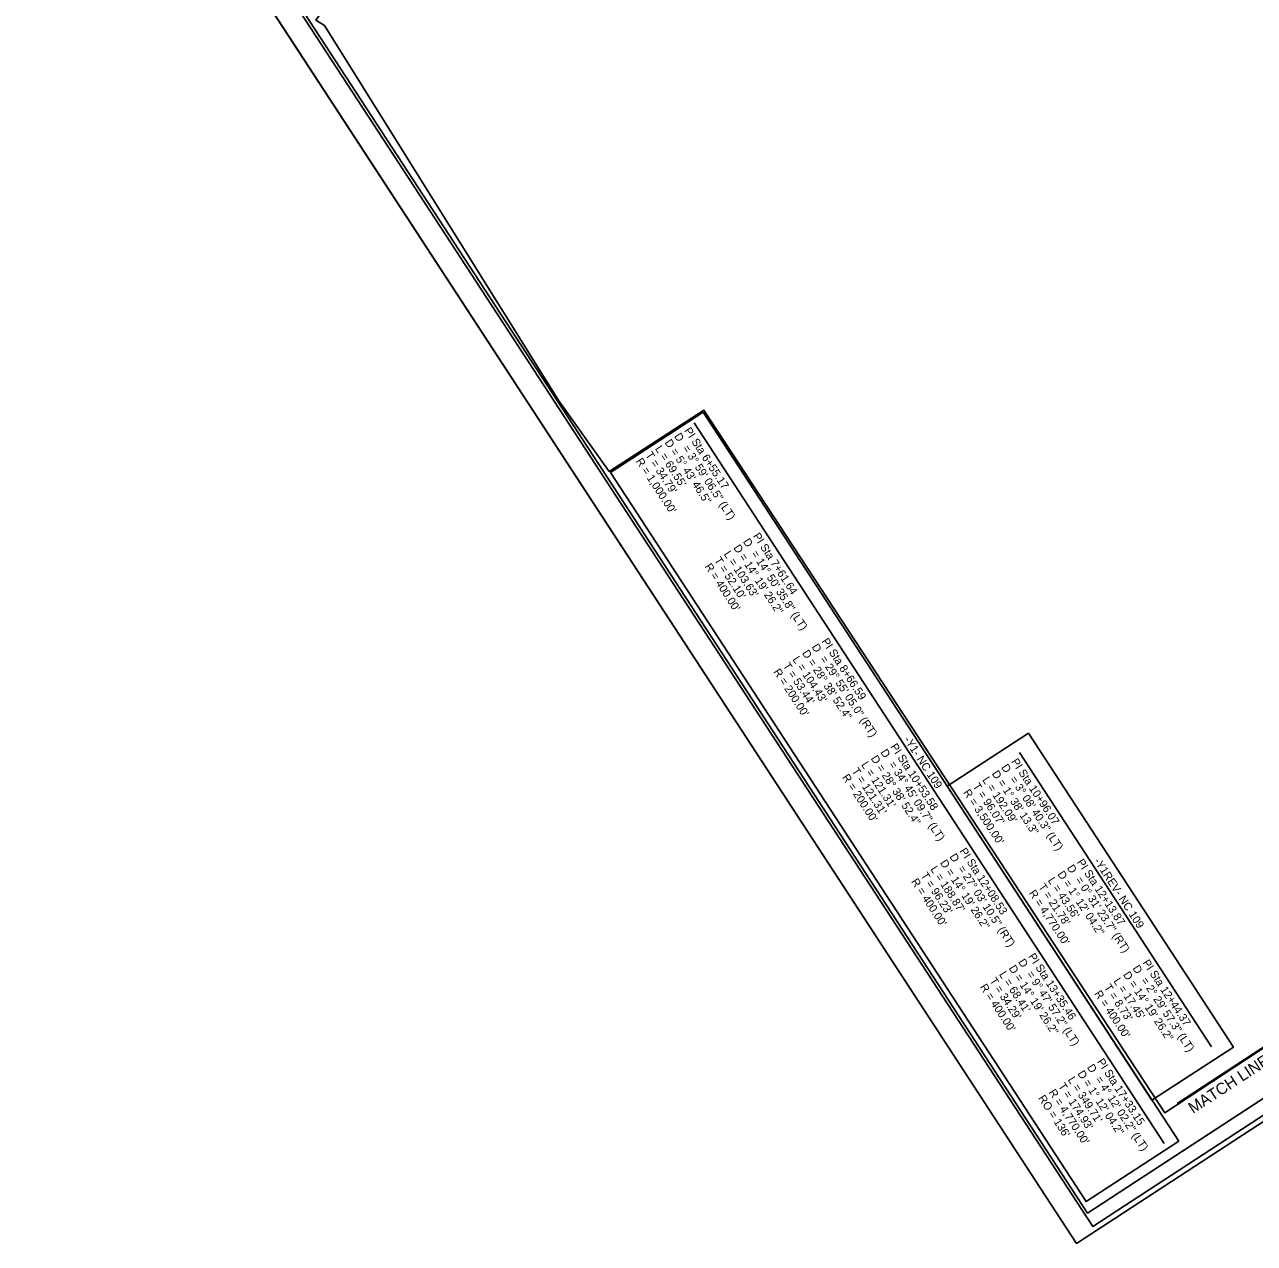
# Model space of a CAD drawing. Extents: x 1639622 to 2864602, y 842655 to 973236.
# Drawn here: x 1639622 to 1640697, y 842655 to 843721 of the extents above; entities that cross this region are included whole.
import ezdxf

# ---------------------------------------------------------------- set-up
doc = ezdxf.new("R2010")
doc.units = 0
for name, color, linetype in [('Matchline', 7, 'Continuous'), ('Matchline Text', 7, 'Continuous'), ('Prop Horizontal Alignment Curve and Spiral Data', 7, 'Continuous'), ('Sheet Clip Boundary CELL', 7, 'Continuous'), ('Sheet Cutting Line CELL', 7, 'Continuous'), ('Sheet Plan CELL', 7, 'Continuous'), ('Sheet Plot Border Inside CELL', 7, 'Continuous'), ('Sheet Plot Border Outside CELL', 7, 'Continuous')]:
    doc.layers.add(name, color=color, linetype=linetype)

msp = doc.modelspace()

# ---------------------------------------------------------------- linework, layer by layer
at = {"layer": 'Matchline'}
msp.add_lwpolyline([(1640629.8, 842777.2), (1640923.5, 842968.8)], dxfattribs=at)
at = {"layer": 'Prop Horizontal Alignment Curve and Spiral Data'}
for p, q in [((1640207.4, 843372.3), (1640618.5, 842742.3)), ((1640491.9, 843084), (1640659.8, 842826.7))]:
    msp.add_line(p, q, dxfattribs=at)
for points in [[(1640215.2, 843381.7), (1640631.2, 842744.2), (1640550.1, 842691.3), (1640134.1, 843328.8)], [(1640499.8, 843101.1), (1640679, 842826.5), (1640607.8, 842780.1), (1640428.6, 843054.7)]]:
    msp.add_lwpolyline(points, close=True, dxfattribs=at)
at = {"layer": 'Sheet Clip Boundary CELL'}
msp.add_lwpolyline([(1640864.1, 843725.8), (1640845.5, 843547.9), (1640966, 843262.5), (1640980.5, 843243.6), (1641082.2, 843071.1), (1640923.5, 842968.8), (1640618.9, 842769.1), (1640215.9, 843383.3), (1640133.1, 843329.9), (1640089, 843391.7), (1639884, 843719.9), (1639876.4, 843724.6), (1639884.6, 843735.9), (1640061.6, 843856.1), (1640079.1, 843868.6), (1640087.5, 843874.1), (1640138.9, 843902.7), (1640120.5, 843922.5), (1640112.3, 843933.1), (1640009.4, 844107.7), (1640616.1, 844499.6)], dxfattribs=at)
at = {"layer": 'Sheet Cutting Line CELL'}
msp.add_line((1639621.8, 844064.7), (1640541.8, 842654.8), dxfattribs=at)
at = {"layer": 'Sheet Plan CELL'}
for points in [[(1641430.7, 843255.1), (1640611, 844511.4), (1639731.7, 843937.6), (1640551.4, 842681.3)], [(1639731.7, 843937.6), (1640611, 844511.4), (1641321.4, 843422.7), (1641195.7, 843340.7), (1641305.1, 843173.1), (1640551.4, 842681.3)]]:
    msp.add_lwpolyline(points, close=True, dxfattribs=at)
at = {"layer": 'Sheet Plot Border Inside CELL'}
msp.add_lwpolyline([(1639645.7, 844064.7), (1640556.1, 842669.5), (1641439.6, 843246), (1640529.2, 844641.3)], close=True, dxfattribs=at)
at = {"layer": 'Sheet Plot Border Outside CELL'}
msp.add_lwpolyline([(1639621.8, 844064.7), (1640541.8, 842654.8), (1641458.9, 843253.2), (1640538.9, 844663.1)], close=True, dxfattribs=at)
msp.add_lwpolyline([(1639621.8, 844064.7), (1640541.8, 842654.8), (1641458.9, 843253.2), (1640538.9, 844663.1)], close=True, dxfattribs=at)

# ---------------------------------------------------------------- texts
at = {"layer": 'Matchline Text'}
msp.add_text('MATCH LINE -Y1- STA. 19+50.00 SEE SHEET 06', height=10, rotation=33.1259, dxfattribs=at).set_placement((1640643.7, 842767.9))
at = {"layer": 'Prop Horizontal Alignment Curve and Spiral Data'}
for s, rotation, p in [('PI Sta 6+55.17', 303.1259, (1640198.4, 843365.6)), ('D = 5%%d 43\' 46.5"', 303.1259, (1640181.3, 843355.2)), ('D', 303.1259, (1640189.6, 843360.7)), ("T = 34.79'", 303.1259, (1640164.5, 843344.3)), ("L = 69.55'", 303.1259, (1640172.9, 843349.7)), ('= 3%%d 59\' 06.5" (LT)', 303.1259, (1640196.9, 843350.1)), ("R = 1,000.00'", 303.1259, (1640156.1, 843338.8)), ('D', 303.1259, (1640249.8, 843268.5)), ('PI Sta 7+61.64', 303.1259, (1640258.5, 843273.4)), ("L = 103.63'", 303.1259, (1640233, 843257.6)), ('D = 14%%d 19\' 26.2"', 303.1259, (1640241.4, 843263.1)), ('= 14%%d 50\' 35.8" (LT)', 303.1259, (1640257, 843257.9)), ("R = 400.00'", 303.1259, (1640216.3, 843246.7)), ("T = 52.10'", 303.1259, (1640224.6, 843252.2)), ('PI Sta 8+66.59', 303.1259, (1640318.6, 843181.3)), ('D = 28%%d 38\' 52.4"', 303.1259, (1640301.5, 843171)), ('D', 303.1259, (1640309.9, 843176.4)), ("T = 53.44'", 303.1259, (1640284.7, 843160)), ("L = 104.43'", 303.1259, (1640293.1, 843165.5)), ('= 29%%d 55\' 05.0" (RT)', 303.1259, (1640317.1, 843165.8)), ("R = 200.00'", 303.1259, (1640276.4, 843154.6)), ('D', 303.1259, (1640370, 843084.3)), ('PI Sta 10+53.58', 303.1259, (1640378.7, 843089.2)), ('-Y1- NC 109', 303.1259, (1640390.6, 843095.3)), ("L = 121.31'", 303.1259, (1640353.2, 843073.4)), ('D = 28%%d 38\' 52.4"', 303.1259, (1640361.6, 843078.8)), ('= 34%%d 45\' 09.7" (LT)', 303.1259, (1640377.2, 843073.7)), ('PI Sta 10+96.07', 303.5147, (1640484.4, 843076.1)), ("R = 200.00'", 303.1259, (1640336.5, 843062.4)), ("T = 121.31'", 303.1259, (1640344.9, 843067.9)), ('D = 1%%d 38\' 13.3"', 303.5147, (1640467.4, 843065.6)), ('D', 303.5147, (1640475.7, 843071.1)), ("T = 96.07'", 303.5147, (1640450.7, 843054.6)), ("L = 192.09'", 303.5147, (1640459.1, 843060.1)), ('= 3%%d 08\' 40.3" (LT)', 303.5147, (1640483.1, 843060.6)), ("R = 3,500.00'", 303.5147, (1640442.4, 843049.1)), ('PI Sta 12+08.53', 303.1259, (1640439.2, 842997.9)), ('D = 14%%d 19\' 26.2"', 303.1259, (1640422.1, 842987.6)), ('D', 303.1259, (1640430.4, 842993)), ('PI Sta 12+13.87', 303.5147, (1640541.8, 842988.2)), ('-Y1REV- NC 109', 303.1259, (1640556.7, 842989.2)), ("T = 96.23'", 303.1259, (1640405.3, 842976.6)), ("L = 188.87'", 303.1259, (1640413.7, 842982.1)), ('= 27%%d 03\' 10.5" (RT)', 303.1259, (1640437.7, 842982.4)), ('D = 1%%d 12\' 04.2"', 303.5147, (1640524.8, 842977.7)), ('D', 303.5147, (1640533.1, 842983.2)), ("R = 400.00'", 303.1259, (1640396.9, 842971.2)), ("T = 21.78'", 303.5147, (1640508.1, 842966.6)), ("L = 43.56'", 303.5147, (1640516.4, 842972.2)), ('= 0%%d 31\' 23.7" (RT)', 303.5147, (1640540.5, 842972.7)), ("R = 4,770.00'", 303.5147, (1640499.8, 842961.1)), ('D', 303.1259, (1640490.5, 842900.9)), ('PI Sta 13+35.46', 303.1259, (1640499.3, 842905.8)), ('PI Sta 12+44.37', 303.5147, (1640599.2, 842900.2)), ("L = 68.41'", 303.1259, (1640473.8, 842890)), ('D = 14%%d 19\' 26.2"', 303.1259, (1640482.2, 842895.4)), ('= 9%%d 47\' 57.2" (LT)', 303.1259, (1640497.8, 842890.3)), ('D = 14%%d 19\' 26.2"', 303.5147, (1640582.2, 842889.8)), ('D', 303.5147, (1640590.5, 842895.3)), ("R = 400.00'", 303.1259, (1640457, 842879)), ("T = 34.29'", 303.1259, (1640465.4, 842884.5)), ("T = 8.73'", 303.5147, (1640565.5, 842878.7)), ("L = 17.45'", 303.5147, (1640573.8, 842884.2)), ('= 2%%d 29\' 57.3" (LT)', 303.5147, (1640597.8, 842884.7)), ("R = 400.00'", 303.5147, (1640557.1, 842873.2)), ('D = 1%%d 12\' 04.2"', 303.1259, (1640542.3, 842803.3)), ('D', 303.1259, (1640550.7, 842808.8)), ('PI Sta 17+33.15', 303.1259, (1640559.4, 842813.7)), ("T = 174.93'", 303.1259, (1640525.5, 842792.4)), ("L = 349.71'", 303.1259, (1640533.9, 842797.9)), ('= 4%%d 12\' 02.2" (LT)', 303.1259, (1640557.9, 842798.2)), ("R = 4,770.00'", 303.1259, (1640517.2, 842786.9)), ("RO = 136'", 303.1259, (1640508, 842781.8))]:
    msp.add_text(s, height=7, rotation=rotation, dxfattribs=at).set_placement(p)

doc.saveas('drawing.dxf')
